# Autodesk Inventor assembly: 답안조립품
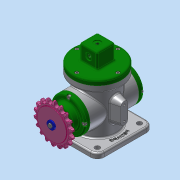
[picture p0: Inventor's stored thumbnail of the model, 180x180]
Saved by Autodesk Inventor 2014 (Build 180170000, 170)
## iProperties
Created: 2021-03
Part Number: 답안조립품
Document SubType Name: Assembly
Designer: net
Author: net
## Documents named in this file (19)
- C:\Users\net\Desktop\710306V1021\답안조립품.iam
- C:\Users\net\Desktop\710306V1021\본체.ipt
- C:\Users\net\Desktop\710306V1021\편심축.ipt
- C:\Users\net\Desktop\710306V1021\베어링 17 x 40 x 12.ipt
- C:\Users\net\Desktop\710306V1021\링크.ipt
- C:\Users\net\Desktop\710306V1021\슬라이더.ipt
- C:\Users\net\Desktop\710306V1021\클레비스 핀 6 x 22.ipt
- 클레비스 핀 6 x 22.ipt
- C:\Users\net\Desktop\710306V1021\E-링.ipt
- C:\Users\net\Desktop\710306V1021\앞커버.ipt
- C:\Users\net\Desktop\710306V1021\뒤커버.ipt
- C:\Users\net\Desktop\710306V1021\오일 실 17 30 8.ipt
- C:\Users\net\Desktop\710306V1021\키 4 x 4 x 12.ipt
- C:\Users\net\Desktop\710306V1021\스프로킷.ipt
- C:\Users\net\Desktop\710306V1021\와셔 4x16.ipt
- C:\Users\net\Desktop\710306V1021\볼트 M4 x 8.ipt
- C:\Users\net\Desktop\710306V1021\덮개.ipt
- C:\Users\net\Desktop\710306V1021\볼트 M4 x 10.ipt
- C:\Users\net\Desktop\710306V1021\멈춤나사 M3.ipt
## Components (1 placed, 1 different names)
1. E-링:1
